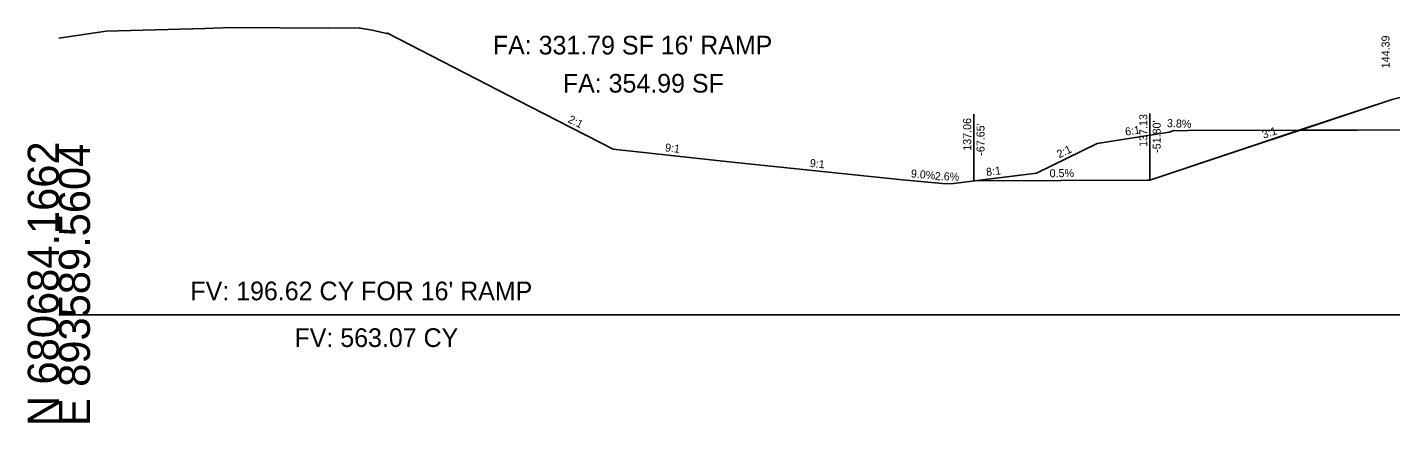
# Model space of a CAD drawing. Extents: x -26 to 4303, y -13 to 10775.
# Drawn here: x 997.2 to 1119.9, y 490.3 to 525.9 of the extents above; entities that cross this region are included whole.
import ezdxf

# ---------------------------------------------------------------- set-up
doc = ezdxf.new("R2010")
doc.units = 0
for name, color, linetype in [('CONST_DCH', 7, 'Continuous'), ('Draft_XS_Grid', 7, 'Continuous'), ('DTM_CORRIDOR', 7, 'Continuous'), ('DTM_X_GROUND', 7, 'Continuous'), ('XS_CELL', 7, 'Continuous'), ('XS_M_SHAPES_EARTHWORK', 7, 'Continuous'), ('XS_P_GROUND', 7, 'Continuous'), ('XS_P_TX_CLEARZONE', 7, 'Continuous'), ('XS_P_TX_FS_BS', 7, 'Continuous'), ('XS_SHEET_EW_TX_AREA', 7, 'Continuous'), ('XS_SHEET_EW_TX_VOLUME', 7, 'Continuous')]:
    doc.layers.add(name, color=color, linetype=linetype)

msp = doc.modelspace()

# ---------------------------------------------------------------- linework, layer by layer
at = {"layer": 'DTM_X_GROUND'}
msp.add_lwpolyline([(1000, 524.89), (1004.27, 525.53), (1013.15, 525.77), (1015.58, 525.87), (1024.31, 525.8), (1027.03, 525.82), (1027.11, 525.8), (1028.2, 525.63), (1029.53, 525.32), (1029.58, 525.36), (1042.44, 518.73), (1049.88, 514.92), (1060.33, 513.78), (1075.94, 512.14), (1079.53, 511.82), (1080.29, 511.8), (1087.99, 512.75), (1093.44, 515.41), (1099.94, 516.44), (1100.36, 516.58), (1101.2, 516.55), (1101.63, 516.59), (1147.17, 516.67)], dxfattribs=at)
at = {"layer": 'XS_CELL'}
msp.add_line((1000, 500), (1150, 500), dxfattribs=at)
at = {"layer": 'XS_P_GROUND'}
for points in [[(1130.76, 522.08), (1120, 519.39), (1098.2, 512.13)], [(1082.35, 512.06), (1097.97, 512.13), (1098.2, 512.13)]]:
    msp.add_lwpolyline(points, dxfattribs=at)
at = {"layer": 'XS_P_TX_CLEARZONE'}
for p, q in [((1082.35, 512.06), (1082.35, 518.06)), ((1082.35, 512.06), (1082.35, 518.06)), ((1082.35, 512.06), (1082.35, 518.06)), ((1098.2, 512.13), (1098.2, 518.13)), ((1098.2, 512.13), (1098.2, 518.13))]:
    msp.add_line(p, q, dxfattribs=at)
at = {"layer": 'XS_SHEET_EW_TX_AREA'}
msp.add_lwpolyline([(1120, 519.39), (1111.63, 516.61), (1147.17, 516.67)], dxfattribs=at)
for points in [[(1082.41, 512.06), (1087.99, 512.75), (1093.44, 515.41), (1099.94, 516.44), (1100.36, 516.58), (1101.2, 516.55), (1101.63, 516.59), (1111.63, 516.61), (1098.2, 512.13), (1097.97, 512.13)], [(1082.35, 512.06), (1082.35, 512.05), (1082.41, 512.06)]]:
    msp.add_lwpolyline(points, close=True, dxfattribs=at)

# ---------------------------------------------------------------- texts
at = {"layer": 'CONST_DCH'}
msp.add_text('X', height=0.12, dxfattribs=at).set_placement((1098.17, 512.07))
at = {"layer": 'Draft_XS_Grid'}
msp.add_text('-', height=0.0001, dxfattribs=at).set_placement((1000, 500))
at = {"layer": 'DTM_CORRIDOR'}
msp.add_text('X', height=0.12, dxfattribs=at).set_placement((1082.31, 512))
at = {"layer": 'XS_CELL'}
for s, p in [('N 680684.1662', (1000, 490)), ('E 893589.5604', (1002.8, 490))]:
    msp.add_text(s, height=2.8, rotation=90, dxfattribs=at).set_placement(p)
at = {"layer": 'XS_M_SHAPES_EARTHWORK'}
for s, p in [("FV: 196.62 CY FOR 16' RAMP", (1011.84, 501.32)), ('FV: 563.07 CY', (1021.21, 497.12))]:
    msp.add_text(s, height=1.68, dxfattribs=at).set_placement(p)
at = {"layer": 'XS_P_TX_CLEARZONE'}
for s, p in [('144.39', (1119.76, 522.19)), ('144.39', (1119.76, 522.19)), ('137.13', (1097.96, 515.12)), ('137.13', (1097.96, 515.12)), ('137.06', (1082.11, 514.77)), ('137.06', (1082.11, 514.77)), ('137.06', (1082.11, 514.77)), ("-67.65'", (1083.31, 514.32)), ("-67.65'", (1083.31, 514.32)), ("-67.65'", (1083.31, 514.32)), ("-51.80'", (1099.16, 514.58)), ("-51.80'", (1099.16, 514.58))]:
    msp.add_text(s, height=0.72, rotation=90, dxfattribs=at).set_placement(p)
at = {"layer": 'XS_P_TX_FS_BS'}
for s, rotation, p in [('2:1', 332.8575, (1045.75, 517.37)), ('6:1', 8.9916, (1096.02, 516.12)), ('3.8%', 357.8414, (1099.72, 516.9)), ('3:1', 18.4332, (1108.43, 515.85)), ('9:1', 353.8011, (1054.53, 514.72)), ('2:1', 26.0251, (1090.03, 514.08)), ('9:1', 353.9907, (1067.56, 513.32)), ('9.0%', 354.8389, (1076.66, 512.38)), ('8:1', 7.0438, (1083.5, 512.49)), ('0.5%', 0.2586, (1089.17, 512.39)), ('2.6%', 358.5329, (1078.83, 512.13))]:
    msp.add_text(s, height=0.72, rotation=rotation, dxfattribs=at).set_placement(p)
at = {"layer": 'XS_SHEET_EW_TX_VOLUME'}
for s, p in [("FA: 331.79 SF 16' RAMP", (1039.06, 523.43)), ('FA: 354.99 SF', (1045.36, 520))]:
    msp.add_text(s, height=1.68, dxfattribs=at).set_placement(p)

doc.saveas('drawing.dxf')
